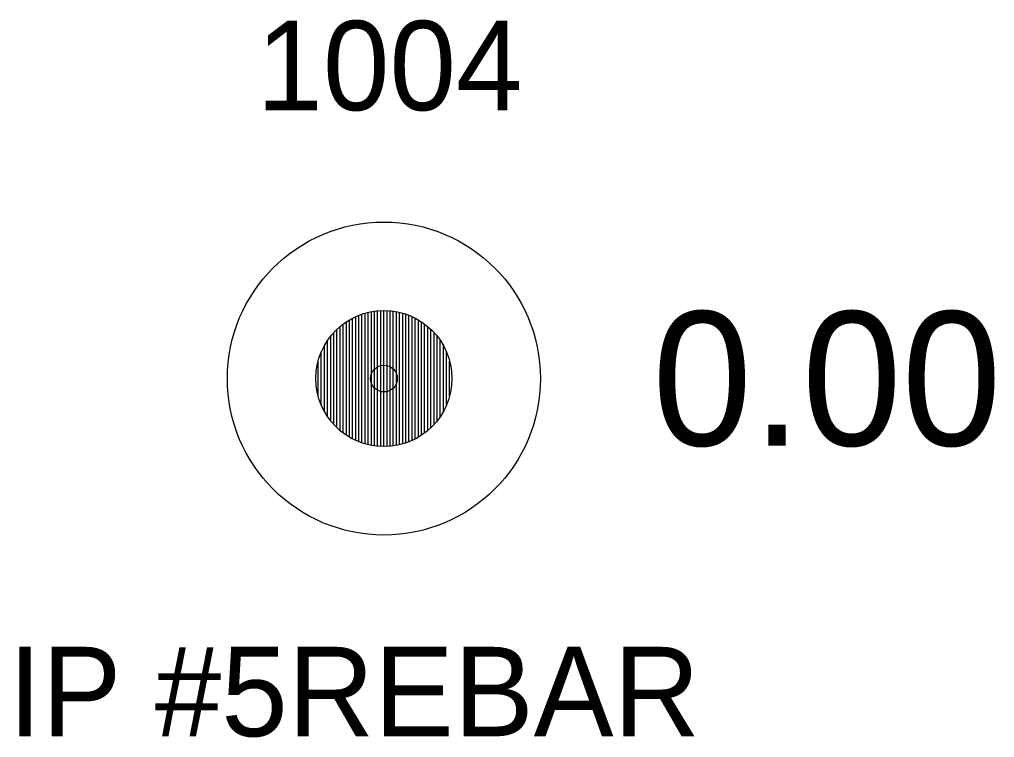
# Model space of a CAD drawing. Extents: x 2274993 to 2278766, y 1075634 to 1076749.
# Drawn here: x 2278754.72 to 2278765.62, y 1075735.21 to 1075743.24 of the extents above; entities that cross this region are included whole.
import ezdxf

# ---------------------------------------------------------------- set-up
doc = ezdxf.new("R2010")
doc.units = 0
for name, color, linetype in [('RD_EX_DV_Prop_txCode', 7, 'Continuous'), ('RD_EX_DV_PropPin', 7, 'Continuous'), ('RD_EX_TX_DV_Prop_ELEV', 7, 'Continuous'), ('RD_SMD_Locator', 7, 'Continuous')]:
    doc.layers.add(name, color=color, linetype=linetype)

msp = doc.modelspace()

# ---------------------------------------------------------------- linework, layer by layer
at = {"layer": 'RD_EX_DV_PropPin'}
for p, q in [((2278758.442, 1075738.549), (2278758.442, 1075739.901)), ((2278758.477, 1075738.532), (2278758.477, 1075739.918)), ((2278758.512, 1075738.517), (2278758.512, 1075739.933)), ((2278758.547, 1075738.505), (2278758.547, 1075739.945)), ((2278758.582, 1075738.494), (2278758.582, 1075739.956)), ((2278758.617, 1075738.484), (2278758.617, 1075739.966)), ((2278758.652, 1075738.477), (2278758.652, 1075739.973)), ((2278758.687, 1075738.471), (2278758.687, 1075739.979)), ((2278758.722, 1075738.467), (2278758.722, 1075739.983)), ((2278758.757, 1075738.465), (2278758.757, 1075739.985)), ((2278758.792, 1075738.464), (2278758.792, 1075739.986)), ((2278758.827, 1075738.465), (2278758.827, 1075739.985)), ((2278758.862, 1075738.467), (2278758.862, 1075739.983)), ((2278758.897, 1075738.471), (2278758.897, 1075739.979)), ((2278758.932, 1075738.477), (2278758.932, 1075739.973)), ((2278758.967, 1075738.484), (2278758.967, 1075739.966)), ((2278759.002, 1075738.494), (2278759.002, 1075739.956)), ((2278759.037, 1075738.505), (2278759.037, 1075739.945)), ((2278759.072, 1075738.517), (2278759.072, 1075739.933)), ((2278759.107, 1075738.532), (2278759.107, 1075739.918)), ((2278759.142, 1075738.549), (2278759.142, 1075739.901)), ((2278758.267, 1075738.674), (2278758.267, 1075739.776)), ((2278758.302, 1075738.643), (2278758.302, 1075739.807)), ((2278758.337, 1075738.615), (2278758.337, 1075739.835)), ((2278758.372, 1075738.59), (2278758.372, 1075739.86)), ((2278758.407, 1075738.569), (2278758.407, 1075739.881)), ((2278759.177, 1075738.569), (2278759.177, 1075739.881)), ((2278759.212, 1075738.59), (2278759.212, 1075739.86)), ((2278759.247, 1075738.615), (2278759.247, 1075739.835)), ((2278759.282, 1075738.643), (2278759.282, 1075739.807)), ((2278759.317, 1075738.674), (2278759.317, 1075739.776)), ((2278758.197, 1075738.751), (2278758.197, 1075739.699)), ((2278758.232, 1075738.71), (2278758.232, 1075739.74)), ((2278759.352, 1075738.71), (2278759.352, 1075739.74)), ((2278759.387, 1075738.751), (2278759.387, 1075739.699)), ((2278758.127, 1075738.855), (2278758.127, 1075739.595)), ((2278758.162, 1075738.798), (2278758.162, 1075739.652)), ((2278759.422, 1075738.798), (2278759.422, 1075739.652)), ((2278759.457, 1075738.855), (2278759.457, 1075739.595)), ((2278758.092, 1075738.927), (2278758.092, 1075739.523)), ((2278759.492, 1075738.927), (2278759.492, 1075739.523)), ((2278758.057, 1075739.029), (2278758.057, 1075739.421)), ((2278759.527, 1075739.029), (2278759.527, 1075739.421))]:
    msp.add_line(p, q, dxfattribs=at)
for radius in [1.75, 0.761]:
    msp.add_circle((2278758.792, 1075739.225), radius, dxfattribs=at)
at = {"layer": 'RD_SMD_Locator'}
msp.add_circle((2278758.792, 1075739.225), 0.15, dxfattribs=at)

# ---------------------------------------------------------------- texts
at = {"layer": 'RD_EX_DV_Prop_txCode'}
for s, p in [('1004', (2278757.367, 1075742.225)), ('IP #5REBAR', (2278754.595, 1075735.225))]:
    msp.add_text(s, height=1, dxfattribs=at).set_placement(p)
at = {"layer": 'RD_EX_TX_DV_Prop_ELEV'}
msp.add_text('0.00', height=1.5, dxfattribs=at).set_placement((2278761.792, 1075738.475))

doc.saveas('drawing.dxf')
